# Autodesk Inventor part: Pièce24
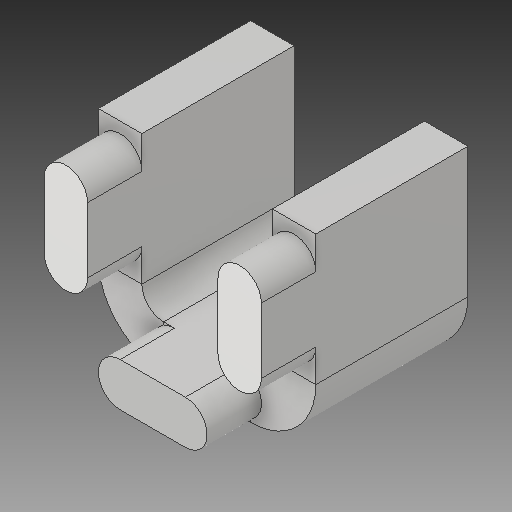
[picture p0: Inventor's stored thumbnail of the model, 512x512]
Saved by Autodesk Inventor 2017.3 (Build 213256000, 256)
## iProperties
Created: 2007-12
Part Number: Pièce24
Material: Générique
Document SubType Name: Modeling
Designer: ficho
Density: 1 g/cm^3
Appearance: Par défaut
Author: ficho
Sending System: SolidWorks 2009
Last Author: christophe
Last Saved: 2011-02-10
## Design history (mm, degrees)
feature "Extru.-Mince2"
node "Solide1"
